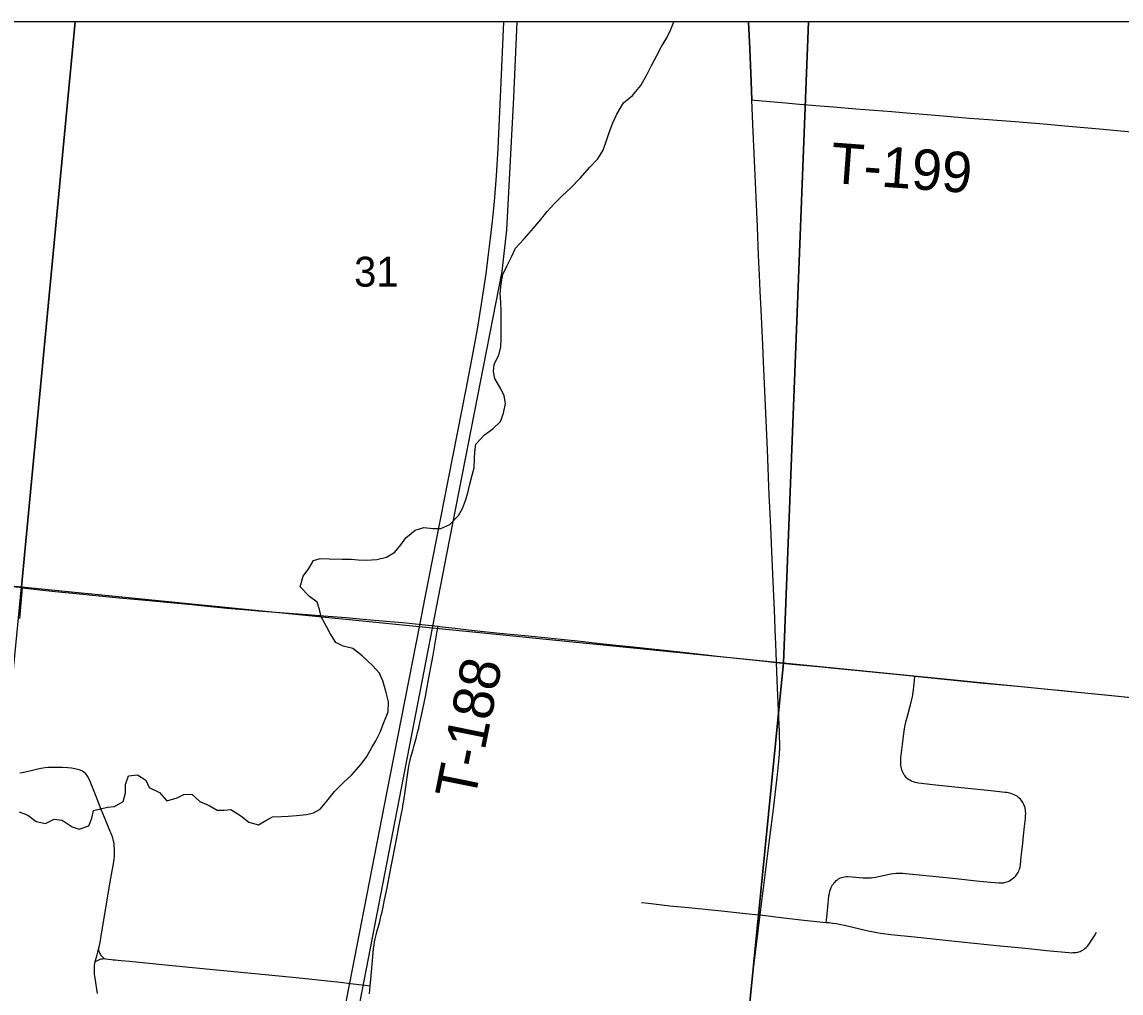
# Model space of a CAD drawing. Extents: x 0 to 1101, y 0 to 440.
# Drawn here: x 839.64 to 841.183, y 380.543 to 381.906 of the extents above; entities that cross this region are included whole.
import ezdxf

# ---------------------------------------------------------------- set-up
doc = ezdxf.new("R2010")
doc.units = 0
for name, color, linetype in [('GM_X_County_Road', 7, 'Continuous'), ('GM_X_Minor_River', 7, 'Continuous'), ('GM_X_Rail_Line', 7, 'Continuous'), ('GM_X_Section', 7, 'Continuous'), ('GM_X_Section_Text', 7, 'Continuous'), ('GM_X_Township_Road', 7, 'Continuous'), ('GM_X_Township_Road_Text', 7, 'Continuous'), ('GM_X_Unincorporated_Text', 7, 'Continuous'), ('GM_X_US_Route', 7, 'Continuous'), ('SH_Cut_Line', 7, 'Continuous')]:
    doc.layers.add(name, color=color, linetype=linetype)

msp = doc.modelspace()

# ---------------------------------------------------------------- linework, layer by layer
at = {"layer": 'GM_X_County_Road'}
msp.add_lwpolyline([(839.2666, 377.0719), (839.8064, 377.0309), (840.2909, 376.9883), (840.8257, 376.9319), (840.9467, 376.9203), (841.3305, 376.8871), (841.3385, 376.8863), (841.3566, 377.073), (841.3964, 377.4824), (841.4351, 377.8808), (841.4843, 378.4003), (841.4936, 378.5206), (841.5774, 379.349), (841.6309, 379.8967), (841.7131, 380.7514), (841.7269, 380.895), (841.796, 381.7031), (841.8133, 381.9059), (839.205, 381.9059)], dxfattribs=at)
at = {"layer": 'GM_X_Minor_River'}
for points in [[(840.2717, 381.2696), (840.2745, 381.2802), (840.2751, 381.2931), (840.2753, 381.3026), (840.277, 381.3132), (840.2893, 381.3262), (840.3009, 381.3348), (840.3117, 381.3448), (840.3157, 381.3565), (840.3185, 381.3701), (840.3168, 381.3812), (840.3121, 381.3911), (840.3036, 381.4053), (840.3015, 381.4153), (840.3028, 381.4255), (840.3091, 381.4383), (840.3119, 381.45), (840.3125, 381.461), (840.3127, 381.4758), (840.3126, 381.4906), (840.3124, 381.5001), (840.3122, 381.5119), (840.3113, 381.5248), (840.3123, 381.5385), (840.3148, 381.5513), (840.321, 381.5641), (840.3273, 381.5773), (840.3325, 381.5882), (840.3448, 381.6013), (840.358, 381.6163), (840.3684, 381.6286), (840.3773, 381.6398), (840.3874, 381.6511), (840.3986, 381.6623), (840.4097, 381.6727), (840.424, 381.6869), (840.4364, 381.7018), (840.4484, 381.7138), (840.4558, 381.7258), (840.4606, 381.7394), (840.4642, 381.7507), (840.4693, 381.7643), (840.4748, 381.7767), (840.4842, 381.7925), (840.4969, 381.8029), (840.5085, 381.8168), (840.5175, 381.8326), (840.5234, 381.845), (840.5312, 381.8589), (840.5375, 381.8713), (840.5453, 381.8837), (840.5504, 381.8946), (840.5551, 381.9059)], [(839.6354, 380.7969), (839.6478, 380.7925), (839.6594, 380.7835), (839.6726, 380.7806), (839.6849, 380.7869), (839.6959, 380.7855), (839.7101, 380.7762), (839.7199, 380.7726), (839.7333, 380.7773), (839.7376, 380.7882), (839.7401, 380.7988), (839.7496, 380.8013), (839.7595, 380.8034), (839.7694, 380.8047), (839.7817, 380.8117), (839.7849, 380.8238), (839.7847, 380.8356), (839.7891, 380.8477), (839.8017, 380.849), (839.8133, 380.8415), (839.8181, 380.8312), (839.8327, 380.8241), (839.8428, 380.8125), (839.8573, 380.8165), (839.8668, 380.8212), (839.8782, 380.8218), (839.8894, 380.8117), (839.9022, 380.8058), (839.9135, 380.7992), (839.9234, 380.7994), (839.9329, 380.8003), (839.9467, 380.7914), (839.9583, 380.7824), (839.9719, 380.7788), (839.9819, 380.7847), (839.9915, 380.7898), (840.0036, 380.7904), (840.0135, 380.7909), (840.0249, 380.7919), (840.039, 380.7931), (840.0489, 380.7956), (840.0584, 380.8008), (840.0677, 380.812), (840.0782, 380.8258), (840.0913, 380.8381), (840.1025, 380.8486), (840.1157, 380.8639), (840.1238, 380.8748), (840.1309, 380.8872), (840.1363, 380.8969), (840.143, 380.9097), (840.1466, 380.9199), (840.1537, 380.9376), (840.1544, 380.9513), (840.1504, 380.9665), (840.1461, 380.981), (840.1418, 380.9917), (840.1317, 381.0025), (840.1175, 381.0161), (840.104, 381.0262), (840.0908, 381.0295), (840.0803, 381.0346), (840.0725, 381.0476), (840.067, 381.0572), (840.0597, 381.0706), (840.0572, 381.0813), (840.0543, 381.0916), (840.0435, 381.0994), (840.0304, 381.1129), (840.0345, 381.128), (840.0422, 381.1385), (840.0489, 381.1498), (840.0584, 381.1526), (840.0709, 381.152), (840.0891, 381.1517), (840.102, 381.1519), (840.1119, 381.1509), (840.1229, 381.1504), (840.138, 381.1512), (840.1514, 381.1544), (840.1633, 381.1618), (840.1714, 381.1719), (840.1788, 381.1816), (840.1919, 381.1924), (840.2041, 381.1964), (840.2169, 381.1946), (840.2279, 381.1948), (840.2402, 381.2003), (840.2525, 381.213), (840.2584, 381.2228), (840.2624, 381.2341), (840.2656, 381.245), (840.2685, 381.2571), (840.2717, 381.2696)]]:
    msp.add_lwpolyline(points, dxfattribs=at)
at = {"layer": 'GM_X_Rail_Line'}
for points in [[(839.8069, 379.0583), (839.831, 379.184), (839.9006, 379.538), (839.9573, 379.828), (840.0035, 380.064), (840.0304, 380.2012), (840.0996, 380.5544), (840.1526, 380.8257), (840.1982, 381.0589), (840.2059, 381.0978), (840.2387, 381.2643), (840.2632, 381.3902), (840.2733, 381.4421), (840.2791, 381.4748), (840.2846, 381.5067), (840.2914, 381.5522), (840.2948, 381.58), (840.2976, 381.6026), (840.3003, 381.6263), (840.303, 381.654), (840.3058, 381.69), (840.3084, 381.7281), (840.3127, 381.8214), (840.3163, 381.9059)], [(840.3347, 381.9059), (840.33, 381.7997), (840.32, 381.614), (840.3133, 381.5557), (840.2356, 381.159), (839.9776, 379.8281), (839.8789, 379.3264), (839.8118, 378.979)]]:
    msp.add_lwpolyline(points, dxfattribs=at)
at = {"layer": 'GM_X_Section'}
for points in [[(840.7091, 381.0063), (840.6089, 379.9958), (839.5404, 380.1007), (839.6388, 381.1131)], [(840.7091, 381.0063), (841.7285, 380.9046), (841.6296, 379.8961), (840.6089, 379.9958)]]:
    msp.add_lwpolyline(points, close=True, dxfattribs=at)
at = {"layer": 'GM_X_Township_Road'}
for points in [[(840.6599, 381.9059), (840.6616, 381.8683), (840.6635, 381.8217), (840.6645, 381.7966)], [(840.6645, 381.7966), (840.6685, 381.7963), (840.7068, 381.7929), (840.7315, 381.7906), (840.76, 381.7884), (840.7791, 381.7867), (840.8107, 381.7841), (840.8483, 381.7812), (840.8613, 381.7802), (840.8818, 381.7784), (840.9051, 381.7764), (840.9331, 381.774), (840.9697, 381.771), (840.9969, 381.7688), (841.04, 381.7655), (841.0798, 381.7624), (841.1039, 381.7603), (841.1527, 381.7559), (841.1979, 381.7518)], [(839.6364, 381.0684), (839.6402, 381.1113), (839.5799, 381.1175)], [(839.6402, 381.1113), (839.6646, 381.1086), (839.6863, 381.1063), (839.711, 381.1038), (839.7479, 381.1003), (839.7765, 381.0976), (839.8131, 381.0941), (839.8782, 381.088), (839.909, 381.0849), (839.927, 381.0832), (839.9567, 381.0805), (839.971, 381.0792), (839.9958, 381.0773), (840.0276, 381.075), (840.0695, 381.0719), (840.0756, 381.0714)], [(840.0756, 381.0714), (840.0948, 381.0697), (840.1188, 381.0676), (840.1511, 381.0648), (840.1746, 381.0627), (840.2102, 381.0591), (840.2239, 381.0575), (840.2258, 381.0572), (840.2472, 381.0548), (840.2744, 381.0516), (840.3108, 381.048), (840.351, 381.044), (840.3784, 381.0413), (840.3965, 381.0393), (840.4195, 381.0369), (840.4436, 381.0342), (840.4602, 381.0326), (840.4787, 381.0307), (840.498, 381.0287), (840.5282, 381.0255), (840.542, 381.0241), (840.5719, 381.0207), (840.6002, 381.0176), (840.6164, 381.0158), (840.6472, 381.0125), (840.6744, 381.0095), (840.6993, 381.0067)], [(840.1277, 380.5414), (840.1287, 380.553), (840.1294, 380.5618), (840.1328, 380.5989), (840.1334, 380.6051), (840.1341, 380.6099), (840.1347, 380.6145), (840.1355, 380.6186), (840.1363, 380.6223), (840.1372, 380.6262), (840.1385, 380.6306), (840.1402, 380.636), (840.142, 380.6432), (840.1432, 380.6479), (840.1442, 380.652), (840.1452, 380.6566), (840.1472, 380.6655), (840.1483, 380.671), (840.1522, 380.6905), (840.1576, 380.718), (840.1654, 380.7582), (840.1688, 380.7759), (840.1731, 380.7972), (840.1738, 380.8009), (840.1745, 380.8051), (840.175, 380.8083), (840.1756, 380.8123), (840.1761, 380.8157), (840.1814, 380.8519), (840.1825, 380.8583), (840.1835, 380.8641), (840.1847, 380.8695), (840.1858, 380.8744), (840.1873, 380.8797), (840.1888, 380.885), (840.1898, 380.8887), (840.1916, 380.8952), (840.1934, 380.9019), (840.1951, 380.9083), (840.1967, 380.9145), (840.1974, 380.9178), (840.2007, 380.9321), (840.2061, 380.9589), (840.2106, 380.9827), (840.2169, 381.0169), (840.2232, 381.0535), (840.2239, 381.0575)], [(840.6993, 381.0067), (840.7205, 381.0045), (840.7581, 381.0009), (840.7807, 380.9987), (840.8191, 380.9949), (840.876, 380.9894), (840.8936, 380.9876), (840.9347, 380.9835), (840.9576, 380.9811), (840.9897, 380.9779), (841.0169, 380.9753), (841.0478, 380.9723), (841.0798, 380.9692), (841.101, 380.9672), (841.1315, 380.9641), (841.1652, 380.9608), (841.1795, 380.9592), (841.2174, 380.9554)], [(841.0424, 380.7288), (841.0434, 380.738), (841.0449, 380.7524), (841.0462, 380.7635), (841.0475, 380.7765), (841.0488, 380.7876), (841.0491, 380.7914), (841.0492, 380.7949), (841.0491, 380.7973), (841.0489, 380.7997), (841.0484, 380.802), (841.0477, 380.8044), (841.0471, 380.8061), (841.0462, 380.8083), (841.0453, 380.81), (841.0443, 380.8115), (841.0431, 380.8131), (841.0417, 380.8146), (841.04, 380.8163), (841.0381, 380.8179), (841.0365, 380.8191), (841.0346, 380.8202), (841.0328, 380.821), (841.0307, 380.8219), (841.0282, 380.8227), (841.0249, 380.8235), (841.0226, 380.824), (841.0201, 380.8244), (841.0001, 380.8265), (840.9632, 380.8305), (840.9182, 380.8349), (840.9106, 380.8357), (840.8988, 380.8372), (840.8963, 380.8377), (840.894, 380.8382), (840.8916, 380.839), (840.8897, 380.8397), (840.8877, 380.8406), (840.8862, 380.8414), (840.8845, 380.8424), (840.883, 380.8435), (840.8816, 380.8449), (840.8803, 380.8465), (840.8792, 380.848), (840.8781, 380.8496), (840.8771, 380.8516), (840.8761, 380.8537), (840.8753, 380.8558), (840.8747, 380.8579), (840.8742, 380.8601), (840.8738, 380.8623), (840.8736, 380.8647), (840.8736, 380.8667), (840.8737, 380.87), (840.8739, 380.873), (840.8761, 380.8915), (840.8778, 380.907), (840.8788, 380.9136), (840.8798, 380.9189), (840.8811, 380.9249), (840.883, 380.9314), (840.8865, 380.944), (840.8885, 380.9512), (840.8894, 380.9548), (840.89, 380.9584), (840.8911, 380.9651), (840.892, 380.9721), (840.893, 380.9821), (840.8936, 380.9876)], [(839.7456, 380.5419), (839.7422, 380.5636), (839.7418, 380.5669), (839.7416, 380.5689), (839.7414, 380.5713), (839.7412, 380.5736), (839.7412, 380.5758), (839.7412, 380.5777), (839.7413, 380.5793), (839.7415, 380.5812), (839.742, 380.5841), (839.7424, 380.5863), (839.7425, 380.5868), (839.7429, 380.5885), (839.7438, 380.5917), (839.7449, 380.5961), (839.7459, 380.5999), (839.747, 380.6041), (839.7478, 380.6073), (839.7492, 380.6135), (839.7503, 380.6199), (839.7511, 380.6257), (839.7545, 380.6449), (839.7606, 380.6817), (839.7643, 380.7038), (839.7683, 380.727), (839.7688, 380.731), (839.7693, 380.735), (839.7694, 380.7384), (839.7695, 380.7423), (839.7694, 380.7457), (839.7692, 380.749), (839.7688, 380.7518), (839.7683, 380.7551), (839.7675, 380.7579), (839.7669, 380.7604), (839.7655, 380.7641), (839.7642, 380.7676), (839.7635, 380.7696), (839.7578, 380.7834), (839.7509, 380.8001), (839.7436, 380.8186), (839.7364, 380.8371), (839.7343, 380.8422), (839.7316, 380.8469), (839.729, 380.8502), (839.7264, 380.8527), (839.7235, 380.8546), (839.7197, 380.8562), (839.7137, 380.8575), (839.7091, 380.8582), (839.7039, 380.8587), (839.6963, 380.8593), (839.6893, 380.8593), (839.684, 380.8594), (839.6792, 380.8593), (839.6758, 380.8591), (839.6719, 380.8587), (839.6658, 380.8578), (839.66, 380.8566), (839.6543, 380.8553), (839.6398, 380.8519), (839.6365, 380.8513)], [(840.769, 380.6419), (840.7698, 380.6494), (840.7711, 380.663), (840.7729, 380.6791), (840.7735, 380.6825), (840.7742, 380.6859), (840.775, 380.6886), (840.7759, 380.6908), (840.777, 380.6929), (840.778, 380.6947), (840.7791, 380.6962), (840.7803, 380.6978), (840.7818, 380.6993), (840.7831, 380.7005), (840.7847, 380.7018), (840.7862, 380.7028), (840.7883, 380.704), (840.7903, 380.7048), (840.7925, 380.7055), (840.7947, 380.7059), (840.7968, 380.7061), (840.7991, 380.7062), (840.8055, 380.7059), (840.8204, 380.7045), (840.8249, 380.7043), (840.8289, 380.7043), (840.8323, 380.7044), (840.8349, 380.7047), (840.8381, 380.7052), (840.8599, 380.7098), (840.8637, 380.7104), (840.8674, 380.7108), (840.8702, 380.711), (840.8736, 380.7111), (840.8767, 380.711), (840.8806, 380.7107), (840.9375, 380.7047), (840.9511, 380.7033), (840.9801, 380.7002), (840.9999, 380.6983), (841.0116, 380.6972), (841.0141, 380.6972), (841.0165, 380.6973), (841.0185, 380.6976), (841.0206, 380.6981), (841.0227, 380.6987), (841.0246, 380.6994), (841.0266, 380.7004), (841.0283, 380.7014), (841.0303, 380.7028), (841.0322, 380.7043), (841.0337, 380.7056), (841.0352, 380.7072), (841.0364, 380.7087), (841.0373, 380.7101), (841.0385, 380.7121), (841.0393, 380.7138), (841.0401, 380.7158), (841.0407, 380.7177), (841.0413, 380.72), (841.0417, 380.7225), (841.0424, 380.7288)], [(840.5098, 380.6697), (840.5196, 380.6686), (840.5496, 380.6653), (840.5757, 380.6627), (840.6221, 380.6581), (840.6474, 380.6554), (840.6696, 380.653), (840.6763, 380.6523)], [(840.6763, 380.6523), (840.7096, 380.6482), (840.7375, 380.6451), (840.769, 380.6419), (840.7726, 380.6415), (840.7783, 380.6408), (840.7835, 380.6401), (840.7894, 380.639), (840.7945, 380.6379), (840.8281, 380.6301), (840.8352, 380.6286), (840.8401, 380.6277), (840.845, 380.6269), (840.8598, 380.6249), (840.893, 380.6214), (840.9364, 380.617), (840.9586, 380.6147), (841.0135, 380.609), (841.0488, 380.6056), (841.0784, 380.6024), (841.1099, 380.5995), (841.113, 380.5993), (841.1154, 380.5994), (841.1178, 380.5995), (841.1201, 380.5998), (841.1223, 380.6002), (841.124, 380.6006), (841.1257, 380.6012), (841.1272, 380.6019), (841.1287, 380.6027), (841.1307, 380.604), (841.1322, 380.605), (841.1341, 380.6067), (841.136, 380.6085), (841.138, 380.6109), (841.1422, 380.6172), (841.1458, 380.6231), (841.1485, 380.6279)], [(839.7549, 380.591), (839.7531, 380.5928), (839.7513, 380.5947), (839.7497, 380.5968), (839.7487, 380.5991), (839.7479, 380.6012), (839.747, 380.6041)], [(839.7425, 380.5868), (839.7456, 380.5884), (839.7476, 380.5894), (839.7493, 380.5901), (839.7509, 380.5906), (839.7526, 380.5909), (839.7549, 380.591), (839.7566, 380.5908), (839.7651, 380.5897), (839.7678, 380.5894), (839.7705, 380.5891), (839.7787, 380.5884), (839.7905, 380.5872), (839.8412, 380.5821), (839.8937, 380.577), (839.9469, 380.5719), (839.971, 380.5697), (840.0248, 380.5646), (840.0553, 380.5614), (840.0863, 380.5579), (840.1008, 380.5559), (840.1124, 380.5545), (840.1216, 380.5537), (840.1287, 380.553)]]:
    msp.add_lwpolyline(points, dxfattribs=at)
at = {"layer": 'GM_X_Unincorporated_Text'}
for points in [[(839.7143, 381.9059), (838.6808, 381.9059), (838.6161, 381.2109), (839.6388, 381.1131)], [(840.7439, 381.9059), (839.7143, 381.9059), (839.6388, 381.1131), (840.7091, 381.0063)], [(841.8136, 381.9059), (840.7439, 381.9059), (840.7091, 381.0063), (841.7285, 380.9046)]]:
    msp.add_lwpolyline(points, close=True, dxfattribs=at)
at = {"layer": 'GM_X_US_Route'}
for points in [[(840.6645, 381.7966), (840.6635, 381.8217), (840.6616, 381.8683), (840.6599, 381.9059)], [(840.6625, 380.5403), (840.668, 380.5847), (840.6735, 380.6298), (840.6763, 380.6523), (840.6894, 380.7574), (840.6944, 380.7969), (840.7008, 380.8493), (840.703, 380.8728), (840.7034, 380.8781), (840.7036, 380.8809), (840.7038, 380.884), (840.7038, 380.887), (840.7038, 380.8897), (840.7038, 380.894), (840.7036, 380.9019), (840.7035, 380.9091), (840.7003, 380.9815), (840.6993, 381.0067), (840.6988, 381.0211), (840.6974, 381.0534), (840.6962, 381.0807), (840.695, 381.1099), (840.6928, 381.1626), (840.6912, 381.1967), (840.6899, 381.2246), (840.689, 381.2416), (840.6863, 381.3051), (840.6827, 381.3883), (840.6809, 381.4286), (840.6798, 381.4528), (840.6775, 381.5017), (840.6763, 381.5282), (840.6755, 381.5506), (840.6741, 381.5779), (840.6725, 381.6182), (840.6707, 381.6598), (840.6687, 381.7013), (840.666, 381.7621), (840.6645, 381.7966)]]:
    msp.add_lwpolyline(points, dxfattribs=at)
at = {"layer": 'SH_Cut_Line'}
msp.add_lwpolyline([(850.9258, 381.9059), (837.3258, 381.9059)], dxfattribs=at)

# ---------------------------------------------------------------- texts
at = {"layer": 'GM_X_Section_Text'}
msp.add_text('31', height=0.04186, rotation=0, dxfattribs=at).set_placement((840.106, 381.5344))
at = {"layer": 'GM_X_Township_Road_Text'}
for s, rotation, p in [('T-199', 355.7742, (840.7737, 381.6801)), ('T-188', 78.6344, (840.2752, 380.8116))]:
    msp.add_text(s, height=0.05682, rotation=rotation, dxfattribs=at).set_placement(p)

doc.saveas('drawing.dxf')
